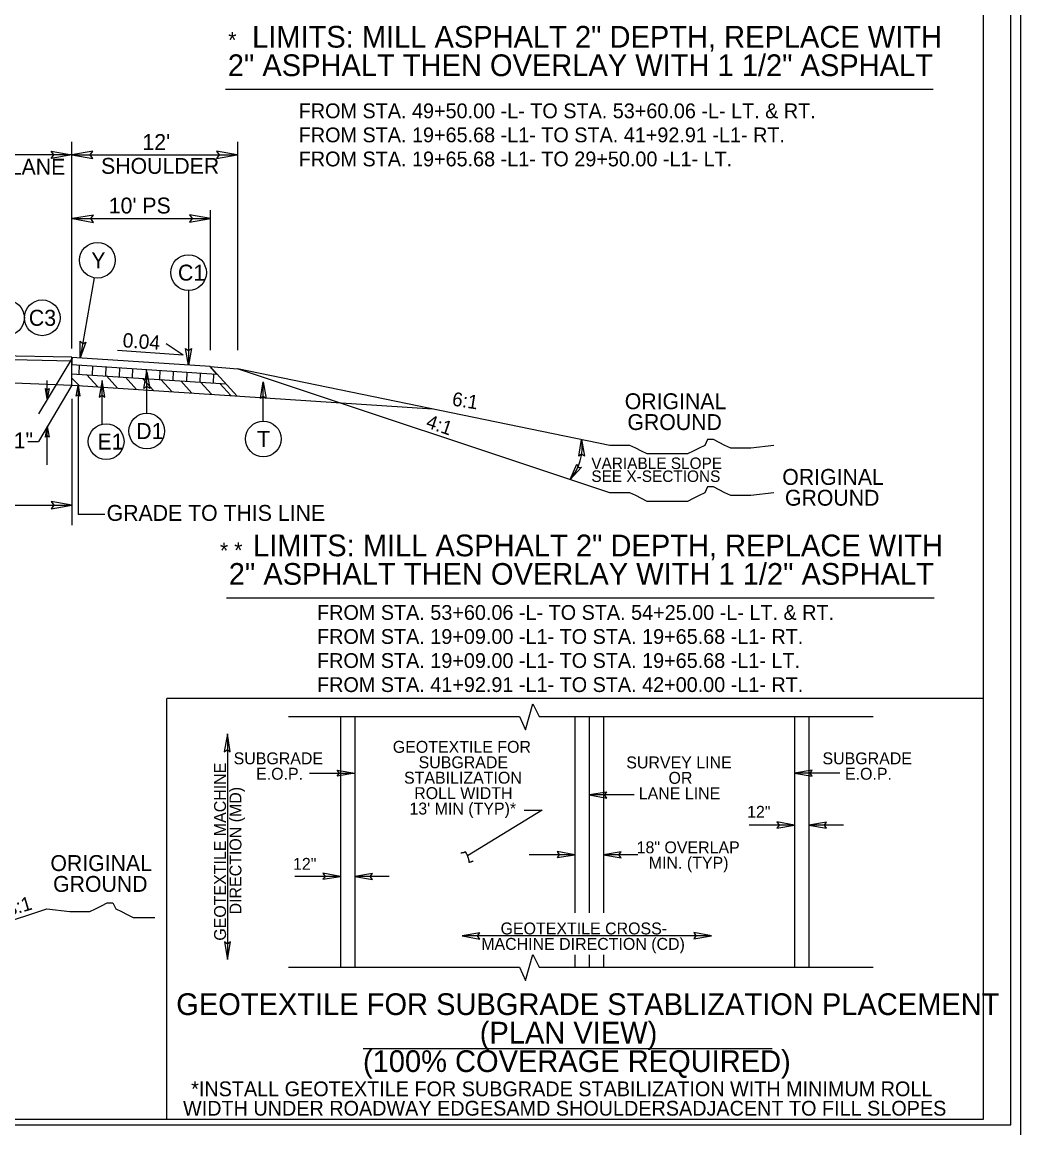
# Model space of a CAD drawing. Extents: x 2176024 to 2177225, y 75947 to 76635.
# Drawn here: x 2176826.2 to 2176898.7, y 76457.9 to 76538.1 of the extents above; entities that cross this region are included whole.
import ezdxf

# ---------------------------------------------------------------- set-up
doc = ezdxf.new("R2010")
doc.units = 0
for name, color, linetype in [('Exist XS Ground Line', 7, 'Continuous'), ('Old_Level_1', 7, 'Continuous'), ('Old_Level_10', 7, 'Continuous'), ('Old_Level_11', 7, 'Continuous'), ('Old_Level_5', 7, 'Continuous'), ('Prop Dimension', 7, 'Continuous'), ('Sheet Plot Border Inside CELL', 7, 'Continuous'), ('Sheet Plot Border Outside CELL', 7, 'Continuous'), ('Sheet Typical CELL', 7, 'Continuous'), ('Typical Curb CELL', 7, 'Continuous'), ('Typical Hinge Slope Arterial CELL', 7, 'Continuous'), ('Typical Pavement Slope CELL', 7, 'Continuous'), ('Typical Pavement Slope Information CELL', 7, 'Continuous'), ('Typical Shoulder Slope CELL', 7, 'Continuous'), ('Typical Slope Point Local CELL', 7, 'Continuous'), ('Typical Terminator CELL', 7, 'Continuous'), ('Typical Text General CELL', 7, 'Continuous'), ('Typical Text Label CELL', 7, 'Continuous')]:
    doc.layers.add(name, color=color, linetype=linetype)

msp = doc.modelspace()

# ---------------------------------------------------------------- linework, layer by layer
at = {"layer": 'Exist XS Ground Line'}
msp.add_line((2176817.841, 76512.243), (2176829.841, 76511.758), dxfattribs=at)
at = {"layer": 'Old_Level_1'}
for p, q in [((2176840.982, 76533.219), (2176892.353, 76533.219)), ((2176830.356, 76512.546), (2176830.38, 76513.215)), ((2176831.343, 76512.478), (2176831.367, 76513.15)), ((2176832.298, 76512.421), (2176832.322, 76513.088)), ((2176833.285, 76512.349), (2176833.309, 76513.023)), ((2176834.235, 76512.288), (2176834.259, 76512.961)), ((2176830.387, 76511.712), (2176829.841, 76512.258)), ((2176831.712, 76511.622), (2176830.893, 76512.518)), ((2176833.157, 76511.524), (2176832.339, 76512.418)), ((2176834.53, 76511.439), (2176833.723, 76512.322)), ((2176835.787, 76511.351), (2176834.96, 76512.241)), ((2176835.222, 76512.231), (2176835.246, 76512.896)), ((2176836.207, 76512.158), (2176836.232, 76512.831)), ((2176837.109, 76511.27), (2176836.3, 76512.155)), ((2176837.195, 76512.097), (2176837.219, 76512.766)), ((2176838.182, 76512.03), (2176838.206, 76512.702)), ((2176839.137, 76511.973), (2176839.161, 76512.639)), ((2176840.124, 76511.9), (2176840.149, 76512.574)), ((2176838.552, 76511.173), (2176837.732, 76512.069)), ((2176839.996, 76511.075), (2176839.178, 76511.969)), ((2176841.37, 76510.99), (2176840.563, 76511.873)), ((2176841.051, 76496.306), (2176892.422, 76496.306)), ((2176850.976, 76463.607), (2176880.666, 76463.607))]:
    msp.add_line(p, q, dxfattribs=at)
at = {"layer": 'Old_Level_10'}
for p, q in [((2176895.987, 76489.023), (2176836.726, 76489.023)), ((2176836.726, 76458.475), (2176836.726, 76489.023)), ((2176849.328, 76487.699), (2176849.328, 76469.508)), ((2176850.367, 76487.699), (2176850.367, 76469.508)), ((2176866.328, 76487.699), (2176866.328, 76473.466)), ((2176867.367, 76487.699), (2176867.367, 76473.466)), ((2176868.405, 76487.699), (2176868.405, 76473.466)), ((2176882.289, 76487.699), (2176882.289, 76469.508)), ((2176883.328, 76487.699), (2176883.328, 76469.508)), ((2176866.328, 76470.419), (2176866.328, 76469.508)), ((2176867.367, 76470.419), (2176867.367, 76469.508)), ((2176868.405, 76470.419), (2176868.405, 76469.508))]:
    msp.add_line(p, q, dxfattribs=at)
at = {"layer": 'Old_Level_11'}
for p, q in [((2176831.463, 76519.542), (2176830.439, 76513.723)), ((2176838.302, 76518.621), (2176838.302, 76513.207)), ((2176835.273, 76509.717), (2176835.273, 76512.714)), ((2176832.032, 76508.955), (2176832.032, 76512.088)), ((2176843.728, 76509.142), (2176843.728, 76511.984)), ((2176862.76, 76486.744), (2176863.291, 76488.637)), ((2176863.291, 76488.637), (2176863.738, 76487.699)), ((2176845.545, 76487.699), (2176862.313, 76487.699)), ((2176862.313, 76487.699), (2176862.76, 76486.744)), ((2176863.738, 76487.699), (2176887.997, 76487.699)), ((2176841.124, 76486.437), (2176841.124, 76470.066)), ((2176847.086, 76483.602), (2176850.367, 76483.602)), ((2176885.57, 76483.602), (2176882.289, 76483.602)), ((2176870.648, 76482.017), (2176867.367, 76482.017)), ((2176863.969, 76480.906), (2176858.537, 76477.592)), ((2176862.667, 76480.906), (2176863.969, 76480.906)), ((2176863.969, 76480.906), (2176863.969, 76480.906)), ((2176882.289, 76479.825), (2176878.984, 76479.825)), ((2176885.83, 76479.825), (2176883.328, 76479.825)), ((2176866.328, 76477.678), (2176863.023, 76477.678)), ((2176870.907, 76477.678), (2176868.405, 76477.678)), ((2176849.328, 76476.106), (2176846.023, 76476.106)), ((2176852.869, 76476.106), (2176850.367, 76476.106)), ((2176876.248, 76471.791), (2176858.157, 76471.791)), ((2176862.76, 76468.553), (2176863.291, 76470.446)), ((2176863.291, 76470.446), (2176863.738, 76469.508)), ((2176845.545, 76469.508), (2176862.313, 76469.508)), ((2176862.313, 76469.508), (2176862.76, 76468.553)), ((2176863.738, 76469.508), (2176887.997, 76469.508))]:
    msp.add_line(p, q, dxfattribs=at)
for points in [[(2176830.851, 76514.869), (2176830.439, 76513.723), (2176830.438, 76514.948), (2176830.622, 76514.76)], [(2176838.509, 76514.407), (2176838.302, 76513.207), (2176838.089, 76514.413), (2176838.302, 76514.26)], [(2176835.066, 76511.514), (2176835.273, 76512.714), (2176835.486, 76511.507), (2176835.273, 76511.66)], [(2176832.239, 76510.888), (2176832.032, 76512.088), (2176831.819, 76510.881), (2176832.032, 76511.034)], [(2176843.521, 76510.784), (2176843.728, 76511.984), (2176843.941, 76510.778), (2176843.728, 76510.931)], [(2176866.616, 76506.605), (2176866.823, 76507.805), (2176867.036, 76506.598), (2176866.823, 76506.751)], [(2176866.826, 76505.788), (2176865.99, 76504.903), (2176866.479, 76506.026), (2176866.572, 76505.781)], [(2176841.334, 76485.154), (2176841.124, 76486.437), (2176840.891, 76485.154), (2176841.124, 76485.318)], [(2176849.085, 76483.812), (2176850.367, 76483.602), (2176849.085, 76483.369), (2176849.248, 76483.602)], [(2176883.571, 76483.812), (2176882.289, 76483.602), (2176883.571, 76483.369), (2176883.408, 76483.602)], [(2176868.649, 76482.227), (2176867.367, 76482.017), (2176868.649, 76481.784), (2176868.486, 76482.017)], [(2176881.007, 76479.615), (2176882.289, 76479.825), (2176881.007, 76480.058), (2176881.17, 76479.825)], [(2176884.61, 76480.035), (2176883.328, 76479.825), (2176884.61, 76479.592), (2176884.447, 76479.825)], [(2176865.046, 76477.468), (2176866.328, 76477.678), (2176865.046, 76477.911), (2176865.209, 76477.678)], [(2176869.687, 76477.888), (2176868.405, 76477.678), (2176869.687, 76477.445), (2176869.524, 76477.678)], [(2176848.046, 76475.896), (2176849.328, 76476.106), (2176848.046, 76476.339), (2176848.209, 76476.106)], [(2176851.649, 76476.316), (2176850.367, 76476.106), (2176851.649, 76475.873), (2176851.486, 76476.106)], [(2176859.439, 76472.001), (2176858.157, 76471.791), (2176859.439, 76471.558), (2176859.276, 76471.791)], [(2176874.966, 76471.581), (2176876.248, 76471.791), (2176874.966, 76472.024), (2176875.129, 76471.791)], [(2176840.914, 76471.348), (2176841.124, 76470.066), (2176841.357, 76471.348), (2176841.124, 76471.185)]]:
    msp.add_lwpolyline(points, close=True, dxfattribs=at)
for centre in [(2176831.688, 76520.819), (2176838.302, 76519.917), (2176825.09, 76516.638), (2176827.682, 76516.638), (2176835.273, 76508.421), (2176832.323, 76507.659), (2176843.728, 76507.846)]:
    msp.add_circle(centre, 1.296, dxfattribs=at)
for points in [[(2176858.057, 76477.816), (2176858.37, 76477.84), (2176858.385, 76477.949), (2176858.537, 76477.592)], [(2176858.537, 76477.592), (2176858.675, 76477.221), (2176858.599, 76477.103), (2176858.967, 76477.221)]]:
    msp.add_open_spline(points, degree=2, dxfattribs=at)
at = {"layer": 'Prop Dimension'}
for p, q in [((2176829.841, 76514.422), (2176829.841, 76529.405)), ((2176841.886, 76514.283), (2176841.886, 76529.405)), ((2176829.841, 76528.468), (2176817.841, 76528.468)), ((2176829.841, 76528.468), (2176841.841, 76528.468)), ((2176839.886, 76514.283), (2176839.886, 76524.45)), ((2176829.886, 76523.833), (2176839.886, 76523.833)), ((2176829.886, 76513.759), (2176827.416, 76509.677)), ((2176829.841, 76511.758), (2176827.416, 76507.663)), ((2176828.052, 76510.752), (2176828.052, 76512.08)), ((2176830.285, 76511.719), (2176830.285, 76502.363)), ((2176829.841, 76510.762), (2176829.841, 76501.58)), ((2176828.052, 76505.963), (2176828.052, 76508.739)), ((2176826.636, 76507.663), (2176827.416, 76507.663)), ((2176805.841, 76503.045), (2176829.841, 76503.045)), ((2176832.219, 76502.363), (2176830.285, 76502.363))]:
    msp.add_line(p, q, dxfattribs=at)
at = {"layer": 'Sheet Plot Border Inside CELL'}
msp.add_lwpolyline([(2176897.987, 76626.883), (2176631.347, 76626.883), (2176631.347, 76458.067), (2176897.987, 76458.067)], close=True, dxfattribs=at)
at = {"layer": 'Sheet Plot Border Outside CELL'}
msp.add_lwpolyline([(2176898.707, 76630.475), (2176629.267, 76630.475), (2176629.267, 76454.475), (2176898.707, 76454.475)], close=True, dxfattribs=at)
at = {"layer": 'Sheet Typical CELL'}
msp.add_lwpolyline([(2176895.987, 76626.475), (2176655.987, 76626.475), (2176655.987, 76458.475), (2176895.987, 76458.475)], close=True, dxfattribs=at)
at = {"layer": 'Typical Curb CELL'}
msp.add_line((2176829.841, 76511.758), (2176829.841, 76513.772), dxfattribs=at)
at = {"layer": 'Typical Hinge Slope Arterial CELL'}
msp.add_arc((2176863.337, 76507.236), 3.532, 318.66964, 9.27204, dxfattribs=at)
at = {"layer": 'Typical Pavement Slope CELL'}
for p, q in [((2176806.511, 76514.008), (2176829.841, 76513.522)), ((2176839.866, 76513.104), (2176829.841, 76513.762)), ((2176829.841, 76513.251), (2176840.367, 76512.56)), ((2176839.866, 76513.104), (2176841.838, 76510.96)), ((2176868.874, 76507.382), (2176841.866, 76512.944)), ((2176829.841, 76512.58), (2176841.023, 76511.846)), ((2176829.886, 76511.745), (2176856.018, 76510.03))]:
    msp.add_line(p, q, dxfattribs=at)
at = {"layer": 'Typical Pavement Slope Information CELL'}
for q in [(2176836.679, 76514.752), (2176833.156, 76514.256)]:
    msp.add_line((2176837.902, 76513.93), q, dxfattribs=at)
at = {"layer": 'Typical Shoulder Slope CELL'}
for p, q in [((2176839.866, 76513.104), (2176841.866, 76512.944)), ((2176868.874, 76503.942), (2176841.866, 76512.944)), ((2176820.363, 76471.207), (2176828.008, 76473.755))]:
    msp.add_line(p, q, dxfattribs=at)
at = {"layer": 'Typical Slope Point Local CELL'}
for p, q in [((2176806.511, 76514.008), (2176829.841, 76513.522)), ((2176829.841, 76513.772), (2176806.561, 76514.257)), ((2176829.841, 76513.522), (2176829.841, 76513.772)), ((2176839.866, 76513.104), (2176829.841, 76513.762)), ((2176829.841, 76513.762), (2176829.841, 76513.251)), ((2176829.841, 76513.251), (2176840.367, 76512.56)), ((2176840.367, 76512.56), (2176839.866, 76513.104))]:
    msp.add_line(p, q, dxfattribs=at)
for points in [[(2176880.78, 76507.382), (2176879.109, 76507.174), (2176878.691, 76507.174), (2176878.064, 76507.174), (2176877.646, 76507.174), (2176877.229, 76507.382), (2176876.811, 76507.592), (2176876.393, 76507.802), (2176875.976, 76507.802), (2176875.766, 76507.382), (2176875.348, 76507.174), (2176874.931, 76506.965), (2176874.513, 76506.757), (2176874.095, 76506.757), (2176873.678, 76506.757), (2176873.26, 76506.757), (2176872.842, 76506.757), (2176872.425, 76506.757), (2176872.007, 76506.757), (2176871.59, 76506.757), (2176871.172, 76506.965), (2176870.754, 76507.174), (2176870.337, 76507.382), (2176869.709, 76507.382), (2176869.292, 76507.382), (2176868.874, 76507.382)], [(2176880.78, 76503.942), (2176879.109, 76503.734), (2176878.691, 76503.734), (2176878.064, 76503.734), (2176877.646, 76503.734), (2176877.229, 76503.942), (2176876.811, 76504.151), (2176876.393, 76504.361), (2176875.976, 76504.361), (2176875.766, 76503.942), (2176875.348, 76503.734), (2176874.931, 76503.524), (2176874.513, 76503.316), (2176874.095, 76503.316), (2176873.678, 76503.316), (2176873.26, 76503.316), (2176872.842, 76503.316), (2176872.425, 76503.316), (2176872.007, 76503.316), (2176871.59, 76503.316), (2176871.172, 76503.524), (2176870.754, 76503.734), (2176870.337, 76503.942), (2176869.709, 76503.942), (2176869.292, 76503.942), (2176868.874, 76503.942)], [(2176828.008, 76473.755), (2176829.679, 76473.547), (2176830.096, 76473.547), (2176830.724, 76473.547), (2176831.141, 76473.547), (2176831.559, 76473.755), (2176831.977, 76473.965), (2176832.394, 76474.175), (2176832.812, 76474.175), (2176833.022, 76473.755), (2176833.439, 76473.547), (2176833.857, 76473.338), (2176834.275, 76473.13), (2176834.692, 76473.13), (2176835.11, 76473.13), (2176835.528, 76473.13), (2176835.867, 76473.13)]]:
    msp.add_lwpolyline(points, dxfattribs=at)
at = {"layer": 'Typical Terminator CELL'}
for points in [[(2176828.331, 76528.728), (2176829.841, 76528.468), (2176828.323, 76528.2), (2176828.516, 76528.468)], [(2176831.35, 76528.728), (2176829.841, 76528.468), (2176831.359, 76528.2), (2176831.166, 76528.468)], [(2176840.331, 76528.208), (2176841.841, 76528.468), (2176840.323, 76528.736), (2176840.516, 76528.468)], [(2176831.395, 76524.093), (2176829.886, 76523.833), (2176831.404, 76523.564), (2176831.211, 76523.833)], [(2176838.376, 76523.573), (2176839.886, 76523.833), (2176838.368, 76524.101), (2176838.561, 76523.833)], [(2176828.185, 76511.507), (2176828.052, 76510.752), (2176827.921, 76511.512), (2176828.054, 76511.415)], [(2176830.155, 76510.964), (2176830.285, 76511.719), (2176830.419, 76510.96), (2176830.285, 76511.056)], [(2176827.92, 76507.984), (2176828.052, 76508.739), (2176828.184, 76507.979), (2176828.05, 76508.076)], [(2176828.331, 76502.785), (2176829.841, 76503.045), (2176828.323, 76503.313), (2176828.516, 76503.045)]]:
    msp.add_lwpolyline(points, close=True, dxfattribs=at)

# ---------------------------------------------------------------- texts
at = {"layer": 'Old_Level_11'}
for s, rotation, p in [('*', 0.00026, (2176841.177, 76536.22)), ('Y', 0.00026, (2176831.243, 76520.239)), ('C1', 0.00026, (2176837.533, 76519.337)), ('C3', 0.00026, (2176826.709, 76516.058)), ('D1', 0.00026, (2176834.5, 76507.841)), ('E1', 0.00026, (2176831.694, 76507.079)), ('T', 359.99974, (2176843.271, 76507.266)), ('*', 0.00026, (2176840.58, 76499.168)), ('*', 0.00026, (2176841.614, 76499.194))]:
    msp.add_text(s, height=1.16, rotation=rotation, dxfattribs=at).set_placement(p)
msp.add_text('11"', height=1.1533, dxfattribs=at).set_placement((2176824.754, 76507.163))
at = {"layer": 'Old_Level_5'}
for s, height, p in [('GEOTEXTILE FOR', 0.86501, (2176853.126, 76485.072)), ('SUBGRADE', 0.865, (2176841.573, 76484.237)), ('SUBGRADE', 0.865, (2176884.309, 76484.237)), ('SUBGRADE', 0.865, (2176854.997, 76483.952)), ('SURVEY LINE', 0.86501, (2176870.07, 76483.941)), ('E.O.P.', 0.865, (2176843.206, 76483.118)), ('STABILIZATION', 0.86501, (2176853.94, 76482.833)), ('OR', 0.865, (2176873.136, 76482.822)), ('E.O.P.', 0.865, (2176885.942, 76483.118)), ('ROLL WIDTH', 0.865, (2176854.679, 76481.713)), ('LANE LINE', 0.865, (2176870.976, 76481.702)), ("13' MIN (TYP)*", 0.86501, (2176854.334, 76480.594)), ('12"', 0.865, (2176878.838, 76480.357)), ('18" OVERLAP', 0.86501, (2176870.821, 76477.779)), ('12"', 0.865, (2176845.885, 76476.581)), ('MIN. (TYP)', 0.865, (2176871.705, 76476.66)), ('GEOTEXTILE CROSS-', 0.86501, (2176860.947, 76471.893)), ('MACHINE DIRECTION (CD)', 0.86501, (2176859.542, 76470.773))]:
    msp.add_text(s, height=height, dxfattribs=at).set_placement(p)
for s, p in [('GEOTEXTILE MACHINE', (2176841.022, 76471.437)), ('DIRECTION (MD)', (2176842.142, 76473.343))]:
    msp.add_text(s, height=0.86501, rotation=90, dxfattribs=at).set_placement(p)
at = {"layer": 'Typical Hinge Slope Arterial CELL'}
for s, p in [('VARIABLE SLOPE', (2176867.534, 76505.666)), ('SEE X-SECTIONS', (2176867.534, 76504.727))]:
    msp.add_text(s, height=0.83438, dxfattribs=at).set_placement(p)
at = {"layer": 'Typical Pavement Slope Information CELL'}
msp.add_text('0.04', height=1.0429, rotation=355.73416, dxfattribs=at).set_placement((2176833.49, 76514.505))
at = {"layer": 'Typical Slope Point Local CELL'}
for s, rotation, p in [('6:1', 351.04182, (2176857.38, 76510.278)), ('4:1', 341.04105, (2176855.464, 76508.697)), ('3:1', 16.46494, (2176825.23, 76473.195))]:
    msp.add_text(s, height=1.0064, rotation=rotation, dxfattribs=at).set_placement(p)
at = {"layer": 'Typical Text General CELL'}
for s, height, p in [("12' ", 1.1533, (2176834.956, 76528.818)), ('TRAVEL LANE', 1.15334, (2176818.899, 76527.027)), ('SHOULDER', 1.1533, (2176831.954, 76527.088)), ("10' PS", 1.1533, (2176832.513, 76524.209)), ('ORIGINAL ', 1.1533, (2176869.958, 76510.007)), ('GROUND', 1.1533, (2176870.152, 76508.495)), ('ORIGINAL ', 1.1533, (2176881.391, 76504.517)), ('GROUND', 1.1533, (2176881.585, 76503.005)), ('GRADE TO THIS LINE', 1.15334, (2176832.358, 76501.903)), ('ORIGINAL', 1.1533, (2176828.277, 76476.493)), ('GROUND', 1.1533, (2176828.471, 76474.981))]:
    msp.add_text(s, height=height, dxfattribs=at).set_placement(p)
at = {"layer": 'Typical Text Label CELL'}
for s, height, p in [('LIMITS: MILL ASPHALT 2" DEPTH, REPLACE WITH', 1.5766, (2176842.913, 76536.244)), ('2" ASPHALT THEN OVERLAY WITH 1 1/2" ASPHALT', 1.5766, (2176841.151, 76534.177)), ('FROM STA. 49+50.00 -L- TO STA. 53+60.06 -L- LT. & RT.', 1.0742, (2176846.299, 76531.12)), ('FROM STA. 19+65.68 -L1- TO STA. 41+92.91 -L1- RT.', 1.0742, (2176846.299, 76529.375)), ('FROM STA. 19+65.68 -L1- TO 29+50.00 -L1- LT.', 1.0742, (2176846.299, 76527.629)), ('LIMITS: MILL ASPHALT 2" DEPTH, REPLACE WITH', 1.5766, (2176842.983, 76499.331)), ('2" ASPHALT THEN OVERLAY WITH 1 1/2" ASPHALT', 1.5766, (2176841.221, 76497.264)), ('FROM STA. 53+60.06 -L- TO STA. 54+25.00 -L- LT. & RT.', 1.0742, (2176847.629, 76494.72)), ('FROM STA. 19+09.00 -L1- TO STA. 19+65.68 -L1- RT.', 1.0742, (2176847.629, 76492.974)), ('FROM STA. 19+09.00 -L1- TO STA. 19+65.68 -L1- LT.', 1.0742, (2176847.629, 76491.229)), ('FROM STA. 41+92.91 -L1- TO STA. 42+00.00 -L1- RT.', 1.0742, (2176847.629, 76489.483)), ('GEOTEXTILE FOR SUBGRADE STABLIZATION PLACEMENT', 1.5766, (2176837.407, 76466.043)), ('(PLAN VIEW)', 1.5766, (2176859.435, 76463.976)), ('(100% COVERAGE REQUIRED)', 1.5766, (2176850.961, 76461.909)), ('*INSTALL GEOTEXTILE FOR SUBGRADE STABILIZATION WITH MINIMUM ROLL', 1.0742, (2176838.491, 76460.15)), ('WIDTH UNDER ROADWAY EDGESAMD SHOULDERSADJACENT TO FILL SLOPES', 1.0742, (2176837.903, 76458.742))]:
    msp.add_text(s, height=height, dxfattribs=at).set_placement(p)

doc.saveas('drawing.dxf')
